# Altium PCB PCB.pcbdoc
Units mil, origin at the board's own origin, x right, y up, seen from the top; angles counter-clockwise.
Board outline 1578.55 x 1245 mil, 2 copper layers (Top Layer, Bottom Layer); 4 components, 5 nets, 12 pads, 0 vias.
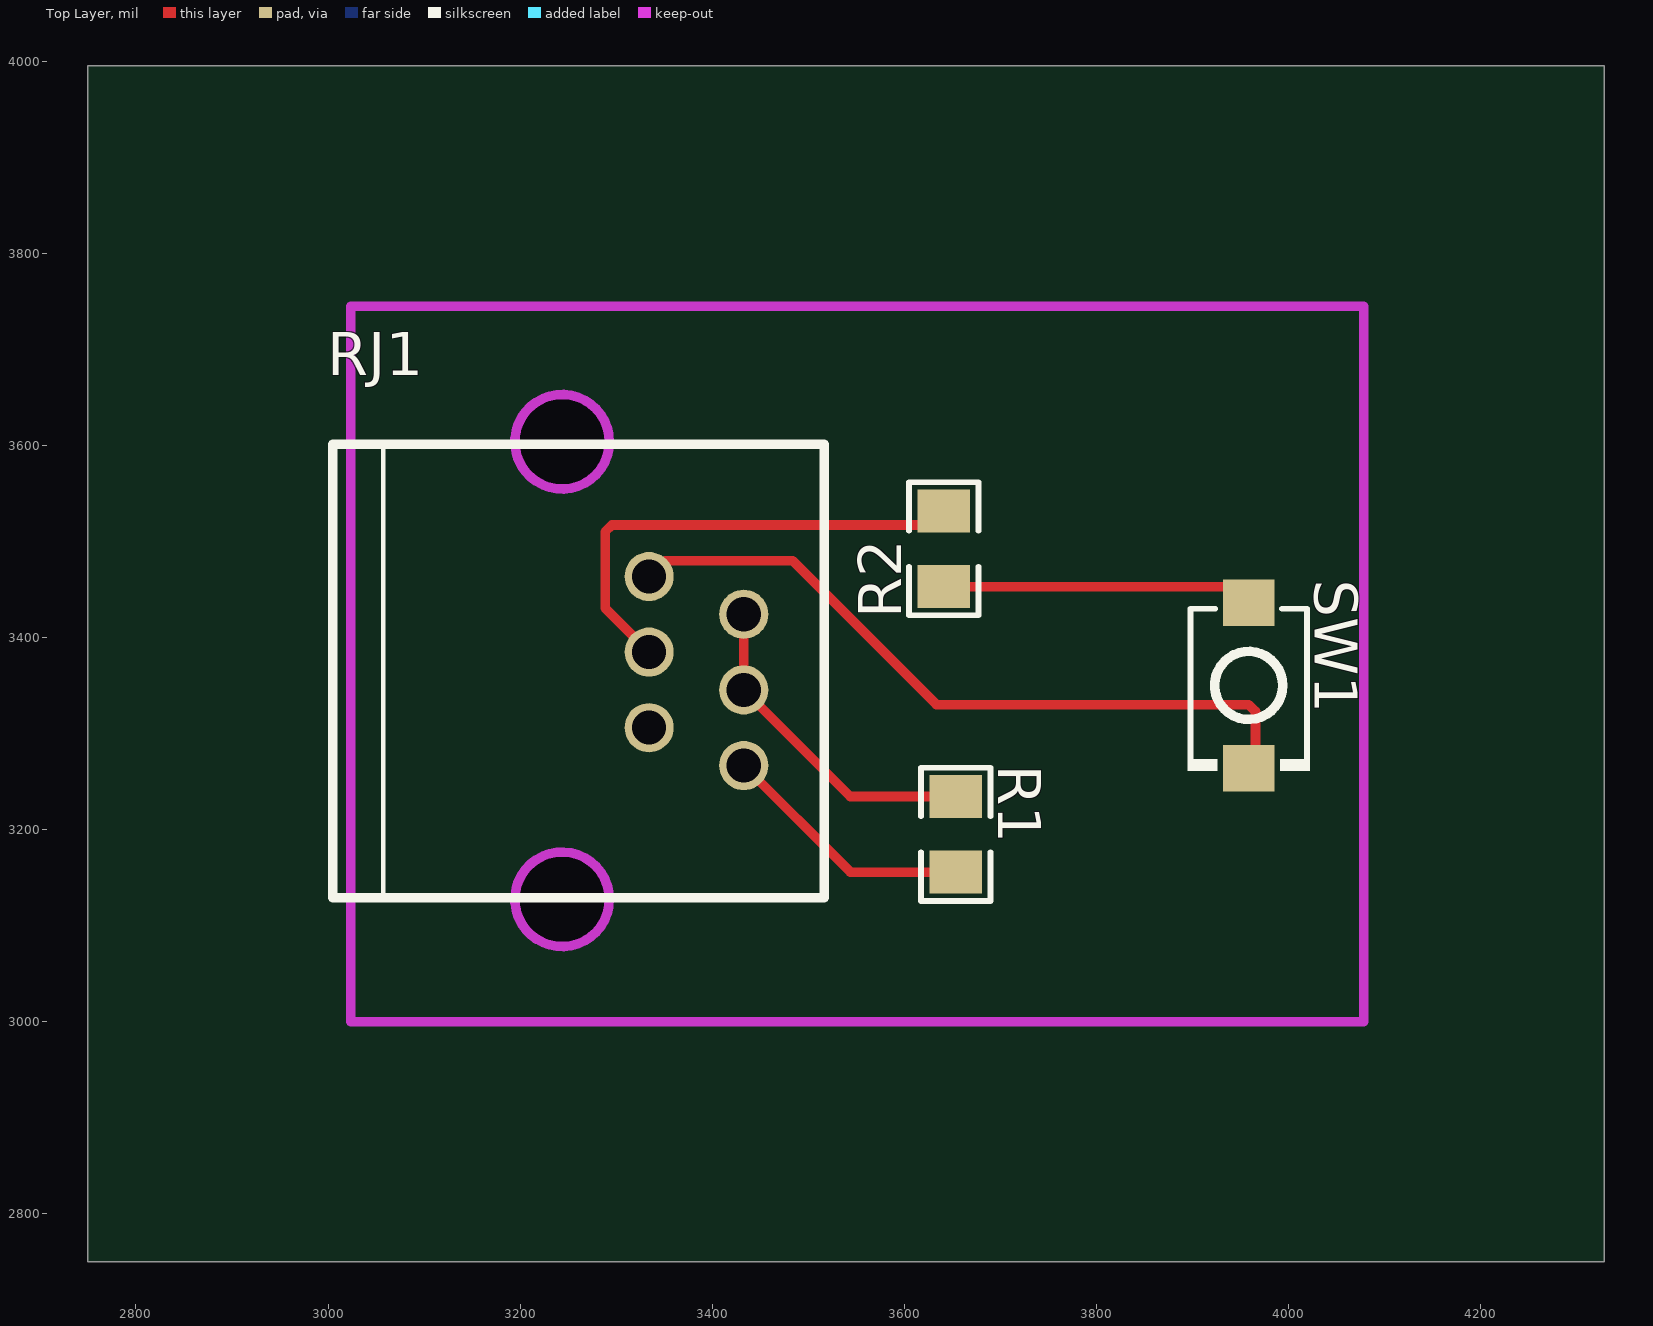
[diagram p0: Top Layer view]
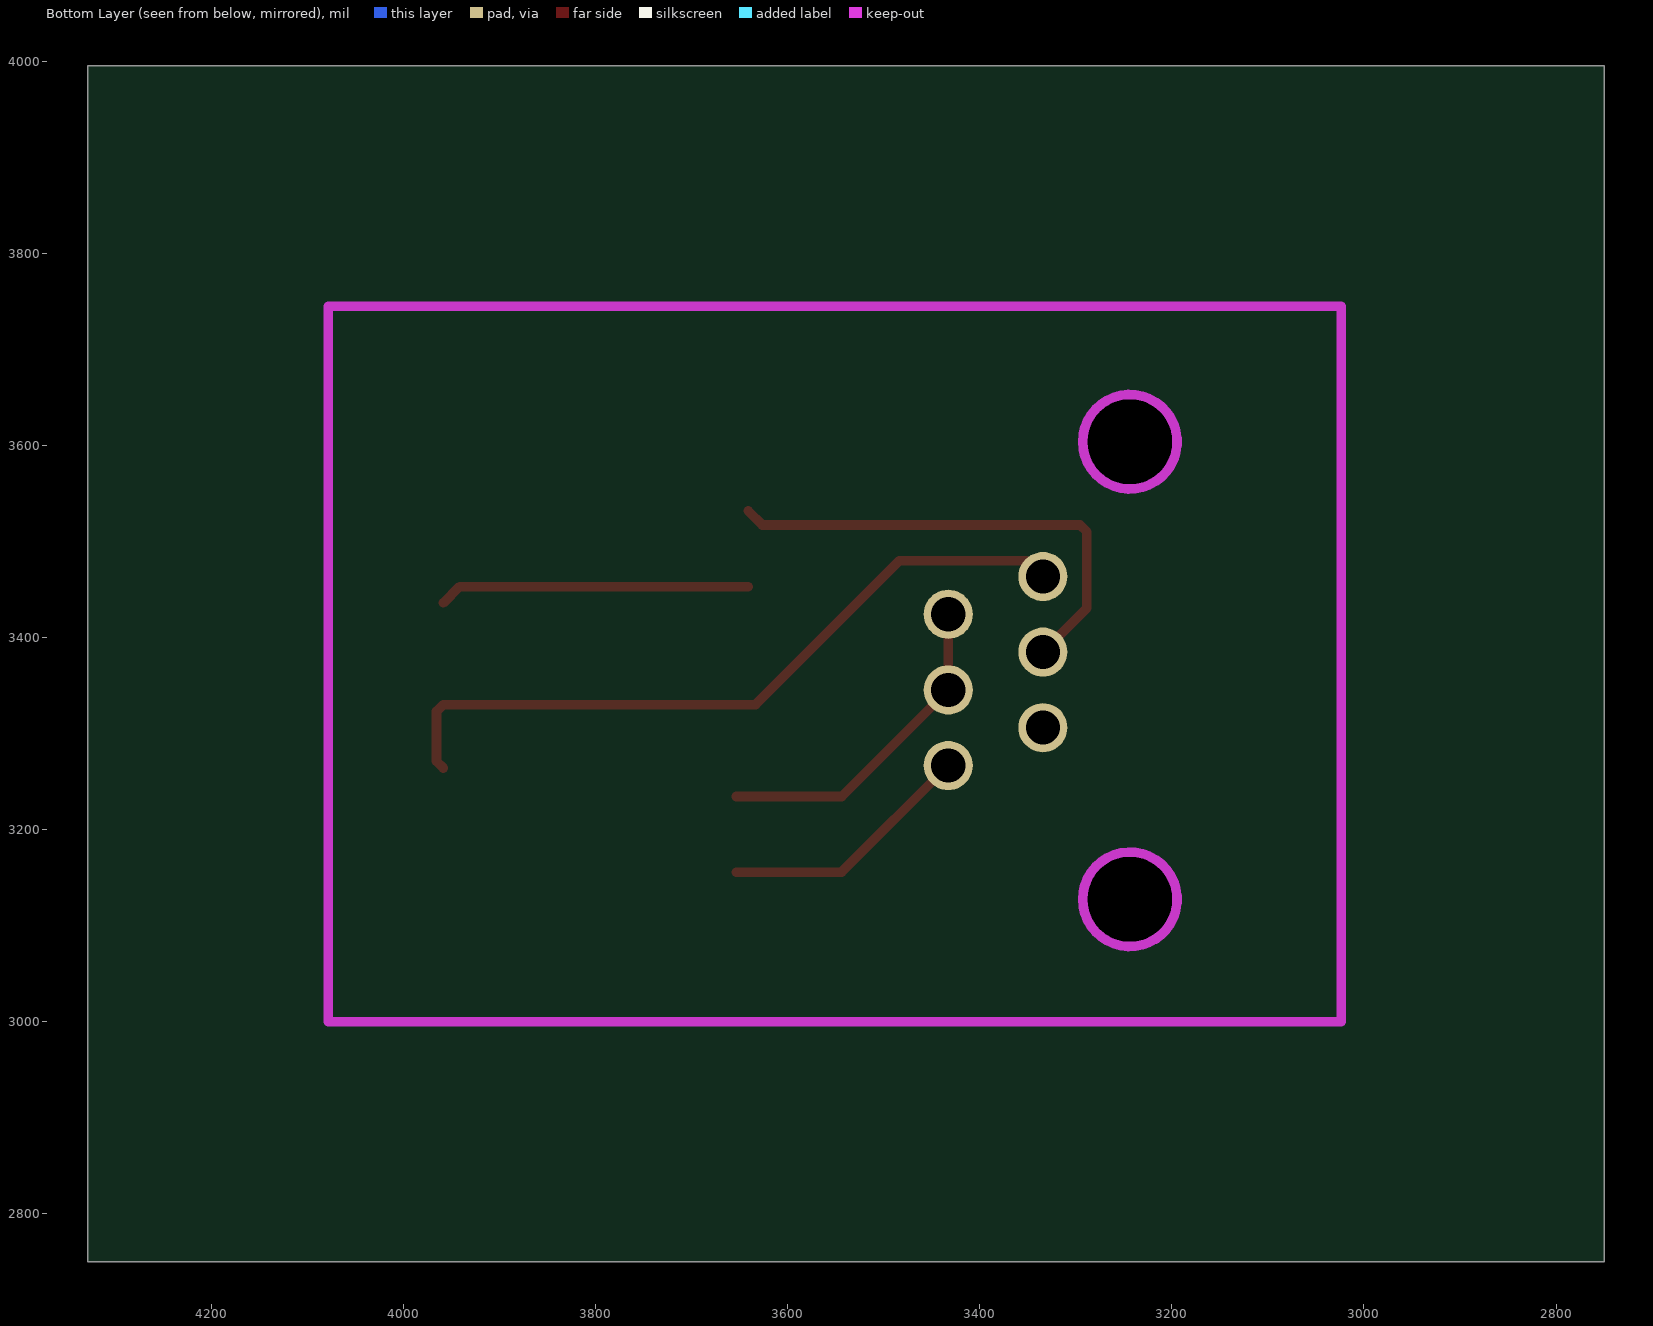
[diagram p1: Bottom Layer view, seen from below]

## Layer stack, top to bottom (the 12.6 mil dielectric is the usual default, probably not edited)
Top Layer: signal copper (thickness not stored)
Dielectric: dielectric 12.6, FR-4, Dk 4.8
Bottom Layer: signal copper (thickness not stored)

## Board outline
4328.55,2750 2750,2750 2750,3995 4328.55,3995

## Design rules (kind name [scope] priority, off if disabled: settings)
Clearance copperThickness1oz [All] p1: gap=7 ignorepadtopadclearanceinfootprint=FALSE except(4: Track-Track; 6: Track-SMDPad SMDPad-SMDPad Track-THPad SMDPad-THPad THPad-THPad Track-Via SMDPad-Via THPad-Via Via-Via SMDPad-Fill THPad-Fill Via-Fill Fill-Fill Track-Region SMDPad-Region THPad-Region Via-Region Region-Region Track-Poly SMDPad-Poly THPad-Poly Via-Poly Fill-Poly Region-Poly Poly-Poly Track-Text SMDPad-Text THPad-Text Via-Text Fill-Text Region-Text Poly-Text Text-Text; 6.9: Track-Hole SMDPad-Hole THPad-Hole Via-Hole Fill-Hole Region-Hole Poly-Hole Text-Hole Sheet-Hole; 11.8: Track-Fill Fill-Region Track-Sheet SMDPad-Sheet THPad-Sheet Via-Sheet Fill-Sheet Region-Sheet Poly-Sheet Text-Sheet)
Clearance copperThickness2oz [All] p1: gap=7 ignorepadtopadclearanceinfootprint=FALSE except(6: Track-SMDPad SMDPad-SMDPad Track-THPad SMDPad-THPad THPad-THPad Track-Via SMDPad-Via THPad-Via Via-Via SMDPad-Fill THPad-Fill Via-Fill Fill-Fill Track-Region SMDPad-Region THPad-Region Via-Region Region-Region Track-Poly SMDPad-Poly THPad-Poly Via-Poly Fill-Poly Region-Poly Poly-Poly Track-Text SMDPad-Text THPad-Text Via-Text Fill-Text Region-Text Poly-Text Text-Text; 6.9: Track-Hole SMDPad-Hole THPad-Hole Via-Hole Fill-Hole Region-Hole Poly-Hole Text-Hole Sheet-Hole; 8: Track-Track; 11.8: Track-Fill Fill-Region Track-Sheet SMDPad-Sheet THPad-Sheet Via-Sheet Fill-Sheet Region-Sheet Poly-Sheet Text-Sheet)
DiffPairsRouting differentialPair [All] p1: maxuncoupledlength=10 maxlimit=6 mostfreqgap=6 toplayer_minwidth=5 toplayer_prefwidth=10 toplayer_maxwidth=100 bottomlayer_minwidth=5 bottomlayer_prefwidth=10 bottomlayer_maxwidth=100
PasteMaskExpansion pasteMaskExpansion [All] p1:
PlaneConnect innerPlane [All] p1: planeconnectstyle=Relief reliefexpansion=20 reliefentries=4 reliefconductorwidth=10 reliefairgap=10
PolygonConnect copperRegion [All] p1: connectstyle=Relief reliefentries=4 reliefconductorwidth=10 polygonreliefangle="90 Angle" airgapwidth=10
RoutingVias viaSize [All] p1: viastyle="Through Hole" holewidth=12.0078 minholewidth=11.811 maxholewidth=248.0314 width=24.0158 minwidth=19.685 maxwidth=393.7008
SolderMaskExpansion solderMaskExpansion [All] p1: useseparateexpansions=TRUE expansion=2 expansionbottom=2
Width copperThickness1oz [All] p1: maxlimit=100 minlimit=5 preferedwidth=10
Width copperThickness2oz [All] p1: maxlimit=100 minlimit=8 preferedwidth=10

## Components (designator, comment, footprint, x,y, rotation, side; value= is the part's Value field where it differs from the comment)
R1 "FRC0805F9100TS" R0805 3653.55,3195 r270 top
R2 "0805W8F2201T5E" R0805 3641.04,3492.32 r90 top
RJ1 "DS1133-S60BPX" RJ11-TH_DS1133-S60BPX 3383.55,3365 r0 top
SW1 "TS-1088-AR02016" SW-SMD_L3.9-W3.0-P4.45 3958.55,3350 r270 top

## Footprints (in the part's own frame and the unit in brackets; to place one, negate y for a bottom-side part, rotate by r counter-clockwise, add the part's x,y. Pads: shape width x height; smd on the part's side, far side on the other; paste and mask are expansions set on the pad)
R0805 [mm]
  rect 1.133x1.377 smd: 1(-1,0) 2(1,0)
  silkscreen extent -1.76,-0.92 1.76,0.92
RJ11-TH_DS1133-S60BPX [mm]
  round 1.3 hole 0.9: 1(1.251,-2.499) 2(-1.251,-1.499) 3(1.251,-0.5) 4(-1.251,0.5) 5(1.251,1.501) 6(-1.251,2.499)
  Multi-Layer board cut-out: -2.302,6.063 -2.473,6.684 -2.93,7.138 -3.552,7.304 -4.174,7.138 -4.631,6.684 -4.802,6.063 -4.802,6.063 -4.631,5.443 -4.174,4.989 -3.552,4.823 -2.93,4.989 -2.473,5.443 -2.302,6.063
  Multi-Layer board cut-out: -2.302,-6.037 -2.473,-5.416 -2.93,-4.962 -3.552,-4.796 -4.174,-4.962 -4.631,-5.416 -4.802,-6.037 -4.802,-6.037 -4.631,-6.657 -4.174,-7.111 -3.552,-7.277 -2.93,-7.111 -2.473,-6.657 -2.302,-6.037
  Multi-Layer keep-out circle w0.254: c-3.552,6.063 r1.25
  Multi-Layer keep-out circle w0.254: c-3.552,-6.037 r1.25
  silkscreen extent -9.62,-6 3.38,6
SW-SMD_L3.9-W3.0-P4.45 [mm]
  rect 1.23x1.36 smd: 1(-2.185,0) 2(2.185,0)
  silkscreen extent -2.03,-1.62 2.25,1.62

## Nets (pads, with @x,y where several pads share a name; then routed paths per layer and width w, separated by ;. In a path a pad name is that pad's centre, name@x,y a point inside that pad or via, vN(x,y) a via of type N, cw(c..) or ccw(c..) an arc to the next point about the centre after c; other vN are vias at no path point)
$1N325: R2.2 RJ1.4 | length 505.7
  Top Layer w10: RJ1.4 3288.55,3430.45 3288.55,3510 3295.62,3517.07 3626.42,3517.07 R2.2
$1N329: R1.2 RJ1.1 | length 266.7
  Top Layer w10: RJ1.1 3543.77,3155.63 R1.2
$1N348: R1.1 RJ1.3 RJ1.5 | length 345.5
  Top Layer w10: RJ1.5 RJ1.3 3543.73,3234.37 R1.1
$1N458: RJ1.6 SW1.2 | length 765.1
  Top Layer w10: RJ1.6 3350.9,3480 3483.55,3480 3633.55,3330 3958.55,3330 3965.62,3322.93 3965.62,3271.05 SW1.2
$1N463: 
pads on no net: R2.1 RJ1.2 SW1.1
copper on no net: | length 324.5
  Top Layer w10: 3641.04,3452.95 3941.62,3452.95 3958.55,3436.02

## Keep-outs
Board Outline Layer:
  lines w10: 3023.55,3000 4078.55,3000 4078.55,3745 3023.55,3745 3023.55,3000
